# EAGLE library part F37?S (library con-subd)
SUB-D
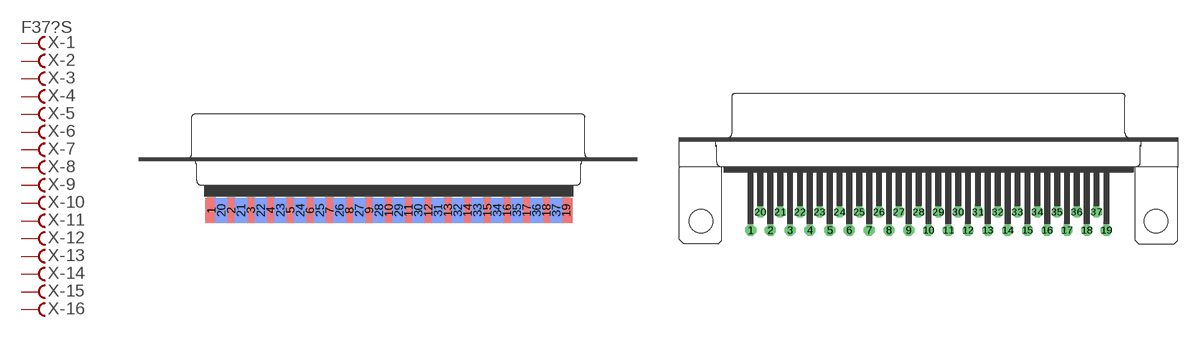
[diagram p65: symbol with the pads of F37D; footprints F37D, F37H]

Designator prefix X; gates -1=FV -2=F -3=F -4=F -5=F -6=F -7=F -8=F -9=F -10=F -11=F -12=F -13=F -14=F -15=F -16=F -17=F -18=F -19=F -20=F -21=F -22=F -23=F -24=F -25=F -26=F -27=F -28=F -29=F -30=F -31=F -32=F -33=F -34=F -35=F -36=F -37=F

## F37DS (OC_FARNELL: unknown; OC_NEWARK: unknown)  [F37D]
1  -1:F  pas
2  -2:F  pas
3  -3:F  pas
4  -4:F  pas
5  -5:F  pas
6  -6:F  pas
7  -7:F  pas
8  -8:F  pas
9  -9:F  pas
10  -10:F  pas
11  -11:F  pas
12  -12:F  pas
13  -13:F  pas
14  -14:F  pas
15  -15:F  pas
16  -16:F  pas
17  -17:F  pas
18  -18:F  pas
19  -19:F  pas
20  -20:F  pas
21  -21:F  pas
22  -22:F  pas
23  -23:F  pas
24  -24:F  pas
25  -25:F  pas
26  -26:F  pas
27  -27:F  pas
28  -28:F  pas
29  -29:F  pas
30  -30:F  pas
31  -31:F  pas
32  -32:F  pas
33  -33:F  pas
34  -34:F  pas
35  -35:F  pas
36  -36:F  pas
37  -37:F  pas

## F37HS (OC_FARNELL: unknown; OC_NEWARK: unknown)  [F37H]
Pads as for F37D

## F37VS (OC_FARNELL: unknown; OC_NEWARK: unknown)  [F37V]
Pads as for F37D

## F37VPS (OC_FARNELL: unknown; OC_NEWARK: unknown)  [F37VP]
Pads as for F37D

## F37VBS (OC_FARNELL: unknown; OC_NEWARK: unknown)  [F37VB]
Pads as for F37D

## F37HPS (OC_FARNELL: unknown; OC_NEWARK: unknown)  [F37HP]
Pads as for F37D

## F37.590S (OC_FARNELL: unknown; OC_NEWARK: unknown)  [177-037-FEMALE]
Pads as for F37D

## Footprint F37D (pad centres in mm)
SUB-D
smd 1.7 x 3.5: 1 -24.689,-6.045; 2 -21.946,-6.045; 3 -19.202,-6.045; 4 -16.459,-6.045; 5 -13.716,-6.045; 6 -10.973,-6.045; 7 -8.23,-6.045; 8 -5.486,-6.045; 9 -2.743,-6.045; 10 0,-6.045; 11 2.743,-6.045; 12 5.486,-6.045; 13 8.23,-6.045; 14 10.973,-6.045; 15 13.716,-6.045; 16 16.459,-6.045; 17 19.202,-6.045; 18 21.946,-6.045; 19 24.689,-6.045
smd 1.7 x 3.5 bottom: 20 -23.317,-6.045; 21 -20.574,-6.045; 22 -17.831,-6.045; 23 -15.088,-6.045; 24 -12.344,-6.045; 25 -9.601,-6.045; 26 -6.858,-6.045; 27 -4.115,-6.045; 28 -1.372,-6.045; 29 1.372,-6.045; 30 4.115,-6.045; 31 6.858,-6.045; 32 9.601,-6.045; 33 12.344,-6.045; 34 15.088,-6.045; 35 17.831,-6.045; 36 20.574,-6.045; 37 23.317,-6.045

## Footprint F37H (pad centres in mm)
SUB-D
drill 1.016 octagon: 1 -24.841,-1.27; 2 -22.073,-1.27; 3 -19.329,-1.27; 4 -16.561,-1.27; 5 -13.792,-1.27; 6 -11.049,-1.27; 7 -8.28,-1.27; 8 -5.512,-1.27; 9 -2.769,-1.27; 10 0,-1.27; 11 2.769,-1.27; 12 5.512,-1.27; 13 8.28,-1.27; 14 11.049,-1.27; 15 13.818,-1.27; 16 16.561,-1.27; 17 19.329,-1.27; 18 22.098,-1.27; 19 24.841,-1.27; 20 -23.47,1.27; 21 -20.701,1.27; 22 -17.932,1.27; 23 -15.189,1.27; 24 -12.421,1.27; 25 -9.652,1.27; 26 -6.909,1.27; 27 -4.14,1.27; 28 -1.372,1.27; 29 1.372,1.27; 30 4.14,1.27; 31 6.909,1.27; 32 9.677,1.27; 33 12.421,1.27; 34 15.189,1.27; 35 17.958,1.27; 36 20.701,1.27; 37 23.47,1.27
hole 3.302 at -31.75,0
hole 3.302 at 31.75,0

## Footprint F37V (pad centres in mm)
SUB-D
drill 1.016 octagon: 1 24.841,1.422; 2 22.073,1.422; 3 19.329,1.422; 4 16.561,1.422; 5 13.792,1.422; 6 11.049,1.422; 7 8.28,1.422; 8 5.512,1.422; 9 2.769,1.422; 10 0,1.422; 11 -2.769,1.422; 12 -5.512,1.422; 13 -8.28,1.422; 14 -11.049,1.422; 15 -13.818,1.422; 16 -16.561,1.422; 17 -19.329,1.422; 18 -22.098,1.422; 19 -24.841,1.422; 20 23.47,-1.422; 21 20.701,-1.422; 22 17.932,-1.422; 23 15.189,-1.422; 24 12.421,-1.422; 25 9.652,-1.422; 26 6.909,-1.422; 27 4.14,-1.422; 28 1.372,-1.422; 29 -1.372,-1.422; 30 -4.14,-1.422; 31 -6.909,-1.422; 32 -9.677,-1.422; 33 -12.421,-1.422; 34 -15.189,-1.422; 35 -17.958,-1.422; 36 -20.701,-1.422; 37 -23.47,-1.422
hole 3.302 at 31.75,0
hole 3.302 at -31.75,0

## Footprint F37VP (pad centres in mm)
SUB-D
drill 1.016 octagon: 1 24.841,1.422; 2 22.073,1.422; 3 19.329,1.422; 4 16.561,1.422; 5 13.792,1.422; 6 11.049,1.422; 7 8.28,1.422; 8 5.512,1.422; 9 2.769,1.422; 10 0,1.422; 11 -2.769,1.422; 12 -5.512,1.422; 13 -8.28,1.422; 14 -11.049,1.422; 15 -13.818,1.422; 16 -16.561,1.422; 17 -19.329,1.422; 18 -22.098,1.422; 19 -24.841,1.422; 20 23.47,-1.422; 21 20.701,-1.422; 22 17.932,-1.422; 23 15.189,-1.422; 24 12.421,-1.422; 25 9.652,-1.422; 26 6.909,-1.422; 27 4.14,-1.422; 28 1.372,-1.422; 29 -1.372,-1.422; 30 -4.14,-1.422; 31 -6.909,-1.422; 32 -9.677,-1.422; 33 -12.421,-1.422; 34 -15.189,-1.422; 35 -17.958,-1.422; 36 -20.701,-1.422; 37 -23.47,-1.422
drill 3.302 pad 5.08 round: G1 -31.75,0; G2 31.75,0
